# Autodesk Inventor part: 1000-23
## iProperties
Created: 2012-08
Part Number: 1000-23
Document SubType Name: Modeling
Designer: Administrator
Density: 0.93 g/cm^3
Material: Rubber
Mass: 0.111229 g
Surface Area: 4.22116 cm^2
Volume: 0.119601 cm^3
Author: Administrator
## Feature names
1. Base1
